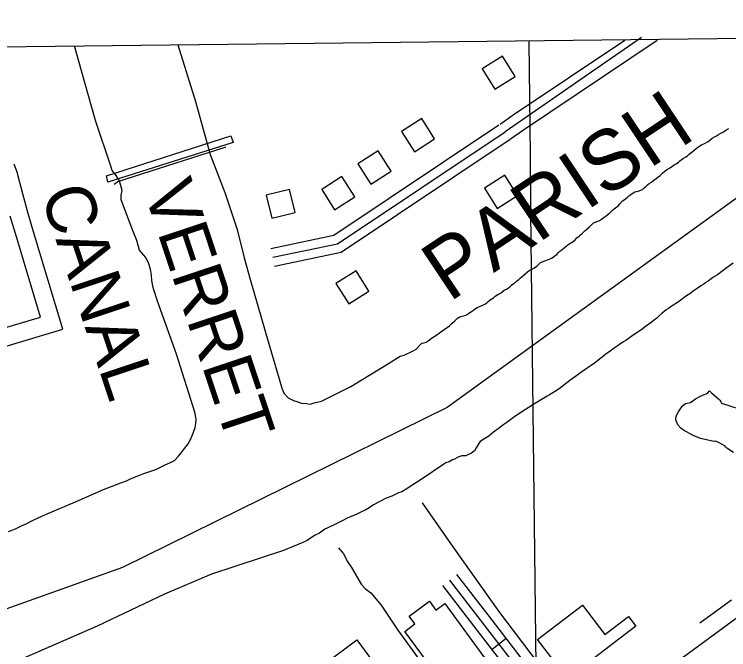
# Model space of a CAD drawing. Extents: x 3683613 to 3738215, y 469626 to 495384.
# Drawn here: x 3692076 to 3693268, y 492267 to 493327 of the extents above; entities that cross this region are included whole.
import ezdxf

# ---------------------------------------------------------------- set-up
doc = ezdxf.new("R2010")
doc.units = 0
for name, color, linetype in [('V-BLDG-OTLN', 7, 'Continuous'), ('V-BRDG-OTLN', 7, 'Continuous'), ('V-GRID-FRAM', 7, 'Continuous'), ('V-GRID-MAJR', 7, 'Continuous'), ('V-RIVR-IDEN', 7, 'Continuous'), ('V-ROAD-CNTR', 7, 'Continuous'), ('V-SITE-VEGE', 7, 'Continuous'), ('V-TOPO-BNDY', 7, 'Continuous'), ('V-TOPO-GNAM-IDEN', 7, 'Continuous'), ('V-TOPO-SHOR', 7, 'Continuous'), ('V-UTIL-LINE', 7, 'Continuous')]:
    doc.layers.add(name, color=color, linetype=linetype)

msp = doc.modelspace()

# ---------------------------------------------------------------- linework, layer by layer
at = {"layer": 'V-BLDG-OTLN'}
for points in [[(3692877.856, 493202.391), (3692911.6520000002, 493223.789), (3692890.254, 493257.58400000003), (3692856.458, 493236.186)], [(3692743.515, 493097.955), (3692777.287, 493119.389), (3692755.853, 493153.161), (3692722.08, 493131.727)], [(3692670.679, 493044.028), (3692704.451, 493065.462), (3692683.017, 493099.234), (3692649.244, 493077.8)], [(3692610.262, 493001.244), (3692644.034, 493022.678), (3692622.6, 493056.45), (3692588.827, 493035.016)], [(3692894.276, 493058.68), (3692860.438, 493037.35000000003), (3692881.767, 493003.512), (3692915.606, 493024.841)], [(3692505.5640000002, 492986.867), (3692544.426, 492996.341), (3692534.951, 493035.20300000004), (3692496.09, 493025.728)], [(3692646.339, 492899.224), (3692612.501, 492877.89400000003), (3692633.83, 492844.056), (3692667.669, 492865.385)], [(3692865.046, 492247.397), (3692799.69, 492199.335), (3692727.338, 492297.717), (3692744.161, 492310.087), (3692734.586, 492323.104), (3692768.593, 492348.114), (3692779.472, 492333.315), (3692794.003, 492343.999)], [(3693113.251, 492306.466), (3692998.881, 492218.881), (3692949.041, 492283.96), (3693023.977, 492341.349), (3693061.511, 492292.335), (3693100.9450000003, 492322.534)], [(3692735.381, 492043.693), (3692589.87, 492240.74700000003), (3692647.522, 492283.319), (3692707.71, 492201.809), (3692724.4080000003, 492214.14), (3692742.899, 492189.097), (3692727.58, 492177.784), (3692794.41, 492087.283)]]:
    msp.add_lwpolyline(points, close=True, dxfattribs=at)
at = {"layer": 'V-BRDG-OTLN'}
msp.add_lwpolyline([(3692229.611, 493057.613), (3692437.292, 493124.447), (3692440.731, 493113.66000000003), (3692231.7800000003, 493047.244)], close=True, dxfattribs=at)
at = {"layer": 'V-GRID-FRAM'}
msp.add_lwpolyline([(3687651.682, 493221.841), (3719350.328, 493590.697), (3719569.827, 475409.35000000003), (3687855.3140000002, 475040.309), (3687651.682, 493221.841)], dxfattribs=at)
at = {"layer": 'V-GRID-MAJR'}
msp.add_spline([(3693141.066, 475101.816), (3693072.329, 481160.385), (3693003.5700000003, 487220.886), (3692934.811, 493281.396), (3692934.789, 493283.31700000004)], degree=3, dxfattribs=at)
at = {"layer": 'V-ROAD-CNTR'}
msp.add_line((3692896.8781673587, 492285.79540232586), (3692873.1312148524, 492267.46243899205), dxfattribs=at)
for points in [[(3693122.6167158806, 493288.8473962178), (3692895.1381708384, 493131.217711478)], [(3693094.86177139, 493283.85040621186), (3692908.588143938, 493158.7866563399)], [(3693148.670663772, 493283.8434062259), (3692925.6741097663, 493134.1287056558)], [(3692908.589143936, 493158.7866563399), (3692886.5951879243, 493143.54668682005)], [(3692503.991953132, 492936.556100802), (3692609.240742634, 492958.5700567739), (3692884.4231922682, 493142.59668872)], [(3692925.675109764, 493134.1287056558), (3692903.6811537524, 493118.88873613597)], [(3692507.06294699, 492921.87413016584), (3692615.150730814, 492944.48208494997), (3692895.1381708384, 493131.217711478)], [(3692510.1339408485, 492907.19215952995), (3692621.060718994, 492930.3941131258), (3692903.461154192, 493118.7387364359)], [(3692062.166341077, 492773.4993945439), (3692156.7476849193, 492802.0505830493), (3692106.191259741, 492970.1267586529), (3692097.685753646, 492998.984228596), (3692089.7038363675, 493027.9019485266), (3692082.210668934, 493057.00364306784), (3692080.9012971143, 493062.3173644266), (3692080.4506362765, 493063.9245098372), (3692080.004188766, 493065.42695452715), (3692079.528816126, 493066.927312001), (3692079.0288159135, 493068.41893943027), (3692078.4990069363, 493069.91083334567), (3692077.9440018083, 493071.3888491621), (3692077.3665370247, 493072.8510425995), (3692076.7623255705, 493074.30642495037), (3692076.1300982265, 493075.7571823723), (3692075.4760194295, 493077.1873071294)], [(3693012.5609359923, 492122.6987285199), (3693890.1881807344, 492767.3854391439), (3694199.0795629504, 492985.8460022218), (3694277.94440522, 493044.8208842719)], [(3692053.6796589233, 492802.2746054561), (3692119.386315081, 492822.1094169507), (3692077.438740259, 492961.56524134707), (3692068.836246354, 492990.75177140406)], [(3692996.989967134, 492111.176751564), (3692927.9571052, 492220.99053193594), (3692802.6533558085, 492383.3022073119)], [(3692866.324228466, 492325.3723231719), (3692814.5263320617, 492392.4681889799)], [(3692842.578275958, 492307.0403598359), (3692790.780379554, 492374.13622564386)], [(3693009.6889417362, 492119.15973559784), (3692940.2720805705, 492229.58551474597), (3692866.323228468, 492325.37332316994)], [(3692984.290992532, 492103.19376752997), (3692915.6421298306, 492212.3955491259), (3692842.5772759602, 492307.04135983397)]]:
    msp.add_lwpolyline(points, dxfattribs=at)
at = {"layer": 'V-SITE-VEGE'}
msp.add_lwpolyline([(3693275.965, 492596.37), (3693264.914, 492603.12700000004), (3693262.9760000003, 492605.59500000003), (3693261.819, 492607.235), (3693249.955, 492613.612), (3693245.575, 492614.94800000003), (3693243.555, 492614.606), (3693227.98, 492617.878), (3693221.203, 492619.68700000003), (3693208.889, 492624.471), (3693192.679, 492633.38800000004), (3693188.358, 492636.728), (3693183.293, 492642.102), (3693179.9280000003, 492650.64), (3693179.6210000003, 492653.864), (3693180.944, 492657.841), (3693184.771, 492664.962), (3693191.065, 492674.018), (3693196.003, 492677.891), (3693204.088, 492679.66000000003), (3693212.698, 492685.434), (3693220.87, 492690.01300000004), (3693224.544, 492691.914), (3693227.79, 492693.02400000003), (3693231.452, 492694.523), (3693233.491, 492695.668), (3693235.9960000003, 492698.805), (3693239.906, 492695.076), (3693250.8850000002, 492685.911), (3693253.222, 492683.433), (3693255.159, 492680.963), (3693256.292, 492678.52), (3693301.2660000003, 492663.93200000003)], dxfattribs=at)
at = {"layer": 'V-TOPO-BNDY'}
msp.add_lwpolyline([(3693656.843302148, 493291.71905653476), (3692798.101177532, 492671.42973931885), (3692256.1794217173, 492404.1458018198), (3691475.0630859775, 492125.56068865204), (3691044.2578277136, 491992.0943891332), (3690569.2766779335, 491705.80691178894), (3690167.234385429, 491293.53288560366), (3689620.055476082, 490480.6831808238), (3689391.3841074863, 490221.66020227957), (3689222.686803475, 490096.86700584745), (3688304.4662702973, 489656.3013151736), (3687696.061298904, 489259.3810567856)], dxfattribs=at)
at = {"layer": 'V-TOPO-SHOR'}
msp.add_line((3693272.856, 492349.875), (3693220.097, 492311.467), dxfattribs=at)
for points in [[(3692348.5371485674, 493276.4951704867), (3692377.8510000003, 493181.783), (3692402.62, 493093.365), (3692427.272, 493029.938), (3692447.469, 492967.976), (3692459.3370000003, 492920.798), (3692469.8880000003, 492883.359), (3692499.593, 492781.407), (3692518.963, 492714.99100000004), (3692521.981, 492703.356), (3692525.41, 492694.9), (3692532.856, 492687.523), (3692541.773, 492682.902), (3692547.078, 492681.022), (3692555.1380000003, 492678.518), (3692563.1890000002, 492677.92), (3692569.548, 492676.89), (3692576.3170000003, 492679.04000000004), (3692588.588, 492681.639), (3692637.4, 492706.01), (3692700.127, 492744.637), (3692719.556, 492757.01300000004), (3692726.114, 492758.527), (3692740.485, 492765.369), (3692746.188, 492768.78500000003), (3692753.356, 492776.021), (3692755.6750000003, 492778.57300000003), (3692759.271, 492779.224), (3692762.867, 492780.088), (3692766.67, 492782.224), (3692773.42, 492787.973), (3692779.122, 492791.60000000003), (3692793.057, 492801.41000000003), (3692802.1350000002, 492807.382)], [(3692066.041, 492464.164), (3692077.6720000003, 492468.66500000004), (3692087.8140000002, 492473.585), (3692096.481, 492477.43700000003), (3692106.198, 492482.776), (3692116.7660000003, 492487.697), (3692125.644, 492491.33900000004), (3692130.504, 492493.69200000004), (3692138.536, 492497.329), (3692177.643, 492513.82), (3692224.782, 492534.16000000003), (3692253.745, 492545.732), (3692263.049, 492548.74), (3692270.8680000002, 492552.588), (3692283.551, 492557.733), (3692292.009, 492560.94800000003), (3692300.046, 492563.74), (3692308.291, 492566.531), (3692312.944, 492568.245), (3692327.313, 492575.514), (3692336.191, 492579.368), (3692343.162, 492583.001), (3692349.906, 492590.235), (3692354.539, 492596.397), (3692360.015, 492602.777), (3692366.122, 492610.43), (3692369.27, 492616.586), (3692372.83, 492625.71), (3692377.434, 492637.59500000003), (3692378.46, 492644.799), (3692379.273, 492652.004), (3692377.102, 492663.219), (3692346.365, 492760.083), (3692314.8200000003, 492848.471), (3692308.1580000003, 492868.984), (3692306.864, 492874.272), (3692305.34, 492882.949), (3692304.875, 492892.054), (3692303.134, 492901.789), (3692300.126, 492911.09500000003), (3692294.9930000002, 492921.66000000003), (3692291.159, 492926.09), (3692284.559, 492933.684), (3692280.037, 492949.974), (3692273.825, 492964.771), (3692254.306, 493017.63), (3692254.269, 493025.678), (3692255.502, 493033.52), (3692250.9820000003, 493049.173), (3692245.432, 493058.467), (3692239.251, 493066.911), (3692237.109, 493071.984), (3692211.117, 493150.229), (3692187.856, 493233.14900000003), (3692176.0302372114, 493274.487822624)], [(3692327.313, 492575.514), (3692336.191, 492579.368), (3692343.162, 492583.001), (3692349.906, 492590.235), (3692354.539, 492596.397), (3692360.015, 492602.777), (3692366.122, 492610.43), (3692369.27, 492616.586), (3692372.83, 492625.71), (3692377.434, 492637.59500000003), (3692378.46, 492644.799), (3692379.273, 492652.004), (3692377.102, 492663.219), (3692346.365, 492760.083), (3692314.8200000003, 492848.471), (3692308.1580000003, 492868.984), (3692306.864, 492874.272), (3692305.34, 492882.949), (3692304.875, 492892.054), (3692303.134, 492901.789), (3692300.126, 492911.09500000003), (3692294.9930000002, 492921.66000000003), (3692291.159, 492926.09), (3692284.559, 492933.684), (3692280.037, 492949.974), (3692273.825, 492964.771), (3692254.306, 493017.63), (3692254.269, 493025.678), (3692255.502, 493033.52), (3692250.9820000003, 493049.173), (3692245.432, 493058.467), (3692239.251, 493066.911), (3692237.109, 493071.984), (3692211.117, 493150.229), (3692187.856, 493233.14900000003), (3692176.0302372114, 493274.487822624)], [(3693153.642, 493058.444), (3693157.703, 493062.071), (3693161.557, 493065.704), (3693164.75, 493068.109), (3693168.342, 493069.874), (3693171.535, 493072.278), (3693174.0870000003, 493074.077), (3693177.0670000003, 493076.278), (3693180.241, 493078.058), (3693184.065, 493080.651), (3693186.414, 493082.664), (3693192.5810000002, 493087.061), (3693196.599, 493089.232), (3693199.157, 493091.239), (3693201.94, 493093.862), (3693206.841, 493097.672), (3693209.6180000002, 493100.088), (3693214.31, 493103.90400000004), (3693217.49, 493105.892), (3693220.048, 493107.897), (3693222.598, 493109.695), (3693227.653, 493111.629), (3693234.001, 493115.188), (3693240.614, 493120.613), (3693244.225, 493123.003), (3693247.608, 493124.777), (3693250.992, 493126.55), (3693254.8030000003, 493128.727), (3693259.452, 493131.08900000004), (3693263.488, 493133.882), (3693268.365, 493136.862)], [(3692802.1350000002, 492807.382), (3692806.43, 492811.83400000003), (3692810.7120000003, 492815.871), (3692813.0700000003, 492818.091), (3692815.626, 492820.098), (3692818.177, 492821.896), (3692823.4390000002, 492823.821), (3692827.42, 492824.745), (3692830.361, 492825.699), (3692833.5500000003, 492827.895), (3692836.095, 492829.484), (3692838.651, 492831.49100000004), (3692842.262, 492833.881), (3692845.248, 492836.292), (3692848.414, 492837.862), (3692853.903, 492840.408), (3692857.487, 492841.967), (3692860.87, 492843.74), (3692864.272, 492846.136), (3692866.83, 492848.143), (3692869.822, 492850.761), (3692872.5810000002, 492852.553), (3692875.339, 492854.34500000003), (3692878.323, 492856.753), (3692882.784, 492859.745), (3692887.433, 492862.107), (3692889.997, 492864.32), (3692893.4050000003, 492866.92600000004), (3692896.995, 492868.693), (3692902.0840000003, 492871.873), (3692905.725, 492875.304), (3692908.93, 492878.124), (3692912.123, 492880.526), (3692914.6750000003, 492882.324), (3692917.659, 492884.735), (3692920.651, 492887.352), (3692924.077, 492890.582), (3692928.3540000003, 492894.41000000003), (3692932.4050000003, 492897.621), (3692934.754, 492899.632), (3692938.7660000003, 492901.596), (3692943.8370000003, 492904.152), (3692948.316, 492907.767), (3692951.105, 492910.599), (3692954.091, 492913.01), (3692961.261, 492916.12700000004), (3692967.157, 492918.451), (3692970.1, 492919.406), (3692973.483, 492921.177), (3692978.1750000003, 492924.995), (3692981.143, 492926.78), (3692983.9450000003, 492930.028), (3692986.3000000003, 492932.249), (3692989.274, 492934.24100000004), (3692993.537, 492937.655), (3692996.949, 492940.467), (3692999.714, 492942.468), (3693002.7, 492944.879), (3693005.461, 492946.67100000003), (3693008.213, 492948.254), (3693011.8340000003, 492951.061), (3693014.839, 492954.09500000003), (3693018.253, 492956.908), (3693020.821, 492959.329), (3693024.032, 492962.358), (3693028.738, 492966.58900000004), (3693031.509, 492968.797), (3693035.986, 492972.412), (3693038.575, 492975.457), (3693042.651, 492979.50200000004), (3693049.384, 492982.009), (3693052.333, 492983.17), (3693055.7290000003, 492985.359), (3693059.987, 492988.564), (3693063.395, 492991.169), (3693066.794, 492993.568), (3693069.5670000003, 492995.775), (3693071.714, 492998.00200000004), (3693074.29, 493000.631), (3693079.185, 493004.234), (3693081.534, 493006.24700000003), (3693083.887, 493008.467), (3693086.2630000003, 493011.31), (3693090.563, 493015.971), (3693093.744, 493017.957), (3693098.436, 493021.775), (3693101.213, 493024.189), (3693104.6210000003, 493026.79600000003), (3693108.451, 493029.596), (3693111.406, 493030.966), (3693117.065, 493032.256), (3693124.22, 493034.96), (3693127.225, 493037.993), (3693129.576, 493040.004), (3693132.566, 493042.623), (3693135.558, 493045.24100000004), (3693139.16, 493047.424), (3693143.639, 493051.039), (3693146.1890000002, 493052.837), (3693150.019, 493055.636), (3693153.642, 493058.444)], [(3693275.6580000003, 492912.25200000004), (3693265.446, 492904.852), (3693258.846, 492899.843), (3693249.271, 492892.841), (3693244.389, 492889.65400000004), (3693241.202, 492887.45900000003), (3693236.742, 492884.469), (3693233.549, 492882.064), (3693230.147, 492879.666), (3693226.538, 492877.276), (3693222.721, 492874.89), (3693213.5870000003, 492868.707), (3693210.185, 492866.309), (3693206.5700000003, 492863.71), (3693203.156, 492860.896), (3693197.848, 492857.306), (3693193.809, 492854.51300000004), (3693188.065, 492850.31), (3693184.032, 492847.723), (3693173.626, 492840.746), (3693167.6750000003, 492836.55), (3693163.8570000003, 492834.166), (3693157.238, 492828.532), (3693152.112, 492824.104), (3693147.842, 492820.483), (3693141.87, 492815.664), (3693137.3910000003, 492812.049), (3693129.953, 492806.858), (3693125.267, 492803.249), (3693119.944, 492799.243), (3693116.336, 492796.851), (3693110.181, 492792.87), (3693102.522, 492787.26900000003), (3693096.148, 492782.878), (3693092.544, 492780.694), (3693088.298, 492777.905), (3693082.132, 492773.50800000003), (3693077.036, 492770.119), (3693072.5700000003, 492766.922), (3693069.805, 492764.92100000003), (3693063.6380000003, 492760.52400000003), (3693059.59, 492757.31200000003), (3693054.683, 492753.294), (3693043.83, 492745.289), (3693038.507, 492741.283), (3693030.2290000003, 492735.907), (3693023, 492730.70900000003), (3693019.176, 492728.114), (3693012.3540000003, 492722.697), (3693007.038, 492718.898), (3693003.001, 492716.105), (3692984.899, 492702.277), (3692977.467, 492697.292), (3692968.779, 492692.137), (3692965.177, 492689.952)], [(3693275.6580000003, 492912.25200000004), (3693265.446, 492904.852), (3693258.846, 492899.843), (3693249.271, 492892.841), (3693244.389, 492889.65400000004), (3693241.202, 492887.45900000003), (3693236.742, 492884.469), (3693233.549, 492882.064), (3693230.147, 492879.666), (3693226.538, 492877.276), (3693222.721, 492874.89), (3693213.5870000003, 492868.707), (3693210.185, 492866.309), (3693206.5700000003, 492863.71), (3693203.156, 492860.896)], [(3693203.156, 492860.896), (3693197.848, 492857.306), (3693193.809, 492854.51300000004), (3693188.065, 492850.31), (3693184.032, 492847.723), (3693173.626, 492840.746), (3693167.6750000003, 492836.55), (3693163.8570000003, 492834.166), (3693157.238, 492828.532), (3693152.112, 492824.104), (3693147.842, 492820.483), (3693141.87, 492815.664), (3693137.3910000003, 492812.049), (3693129.953, 492806.858), (3693125.267, 492803.249), (3693119.944, 492799.243), (3693116.336, 492796.851), (3693110.181, 492792.87), (3693102.522, 492787.26900000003), (3693096.148, 492782.878), (3693092.544, 492780.694), (3693088.298, 492777.905), (3693082.132, 492773.50800000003), (3693077.036, 492770.119), (3693072.5700000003, 492766.922), (3693069.805, 492764.92100000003), (3693063.6380000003, 492760.52400000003), (3693059.59, 492757.31200000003), (3693054.683, 492753.294), (3693043.83, 492745.289), (3693038.507, 492741.283), (3693030.2290000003, 492735.907), (3693023, 492730.70900000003), (3693019.176, 492728.114), (3693012.3540000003, 492722.697), (3693007.038, 492718.898), (3693003.001, 492716.105), (3692984.899, 492702.277), (3692977.467, 492697.292), (3692968.779, 492692.137), (3692965.177, 492689.952), (3692959.457, 492686.583), (3692953.737, 492683.21400000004), (3692949.71, 492680.83400000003), (3692942.725, 492676.87700000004), (3692933.597, 492670.901), (3692928.935, 492668.126), (3692922.781, 492664.145), (3692919.16, 492661.337), (3692910.882, 492655.961), (3692897.484, 492646.36600000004), (3692893.0130000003, 492642.958), (3692883.2260000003, 492635.753), (3692880.031, 492633.351), (3692875.767, 492629.93700000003), (3692871.503, 492626.525), (3692867.667, 492623.517), (3692865.1240000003, 492621.925), (3692859.611, 492618.55), (3692853.4560000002, 492614.569), (3692850.855, 492611.108), (3692849.119, 492608.66000000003), (3692846.684, 492603.737), (3692843.839, 492599.033), (3692838.522, 492595.23600000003), (3692832.808, 492592.074), (3692829.23, 492590.722), (3692826.103, 492590.605), (3692822.7770000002, 492590.706), (3692817.731, 492588.979), (3692814.342, 492586.999), (3692810.5300000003, 492584.822), (3692807.165, 492583.673), (3692804.204, 492582.094), (3692801.2430000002, 492580.517), (3692795.9960000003, 492579.005), (3692792.616, 492576.898)], [(3692965.177, 492689.952), (3692959.457, 492686.583), (3692953.737, 492683.21400000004), (3692949.71, 492680.83400000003), (3692942.725, 492676.87700000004), (3692933.597, 492670.901), (3692928.935, 492668.126), (3692922.781, 492664.145), (3692919.16, 492661.337), (3692910.882, 492655.961), (3692897.484, 492646.36600000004), (3692893.0130000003, 492642.958), (3692883.2260000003, 492635.753), (3692880.031, 492633.351), (3692875.767, 492629.93700000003), (3692871.503, 492626.525), (3692867.667, 492623.517), (3692865.1240000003, 492621.925), (3692859.611, 492618.55), (3692853.4560000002, 492614.569), (3692850.855, 492611.108), (3692849.119, 492608.66000000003), (3692846.684, 492603.737), (3692843.839, 492599.033), (3692838.522, 492595.23600000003), (3692832.808, 492592.074), (3692829.23, 492590.722), (3692826.103, 492590.605), (3692822.7770000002, 492590.706), (3692817.731, 492588.979), (3692814.342, 492586.999), (3692810.5300000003, 492584.822), (3692807.165, 492583.673), (3692804.204, 492582.094), (3692801.2430000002, 492580.517), (3692795.9960000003, 492579.005), (3692792.616, 492576.898), (3692756.514, 492552.16000000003), (3692729.696, 492534.879), (3692722.302, 492530.609), (3692716.8030000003, 492528.678), (3692705.603, 492523.541), (3692696.088, 492519.896), (3692684.89, 492513.916), (3692675.3850000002, 492508.575), (3692667.994, 492503.67), (3692661.233, 492500.037), (3692655.103, 492497.255), (3692647.497, 492493.196), (3692637.9820000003, 492489.55100000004), (3692631.009, 492486.342), (3692624.035, 492482.708), (3692618.332, 492479.716), (3692610.5100000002, 492476.292), (3692600.1580000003, 492470.949), (3692594.028, 492468.168), (3692585.162, 492461.772), (3692577.978, 492458.137), (3692573.3310000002, 492455.574), (3692564.25, 492449.603), (3692557.066, 492446.178), (3692524.933, 492432.89900000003), (3692404.813, 492393.158), (3692326.389, 492359.751), (3692213.958, 492306.49), (3692092.63, 492253.613)], [(3692066.041, 492464.164), (3692077.6720000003, 492468.66500000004), (3692087.8140000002, 492473.585), (3692096.481, 492477.43700000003), (3692106.198, 492482.776), (3692116.7660000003, 492487.697), (3692125.644, 492491.33900000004), (3692130.504, 492493.69200000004), (3692138.536, 492497.329), (3692177.643, 492513.82), (3692224.782, 492534.16000000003), (3692253.745, 492545.732), (3692263.049, 492548.74), (3692270.8680000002, 492552.588), (3692283.551, 492557.733), (3692292.009, 492560.94800000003), (3692300.046, 492563.74), (3692308.291, 492566.531), (3692312.944, 492568.245), (3692327.313, 492575.514)], [(3692792.616, 492576.898), (3692756.514, 492552.16000000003), (3692729.696, 492534.879), (3692722.302, 492530.609), (3692716.8030000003, 492528.678), (3692705.603, 492523.541), (3692696.088, 492519.896), (3692684.89, 492513.916), (3692675.3850000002, 492508.575), (3692667.994, 492503.67), (3692661.233, 492500.037), (3692655.103, 492497.255), (3692647.497, 492493.196), (3692637.9820000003, 492489.55100000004), (3692631.009, 492486.342), (3692624.035, 492482.708), (3692618.332, 492479.716), (3692610.5100000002, 492476.292), (3692600.1580000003, 492470.949), (3692594.028, 492468.168), (3692585.162, 492461.772), (3692577.978, 492458.137), (3692573.3310000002, 492455.574), (3692564.25, 492449.603), (3692557.066, 492446.178), (3692524.933, 492432.89900000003), (3692404.813, 492393.158), (3692326.389, 492359.751), (3692213.958, 492306.49), (3692092.63, 492253.613)], [(3693014.923, 492158.743), (3692886.316, 492329.072), (3692808.161, 492438.582), (3692757.045, 492512.11600000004)], [(3692616.619, 492437.37200000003), (3692625.2660000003, 492427.126), (3692628.625, 492420.99), (3692631.363, 492415.079), (3692638.33, 492404.25800000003), (3692654.37, 492376.516), (3692661.446, 492369.438), (3692671.02, 492362.286), (3692688.095, 492341.38), (3692716.009, 492299.756), (3692833.609, 492137.457), (3692849.616, 492115.543)]]:
    msp.add_lwpolyline(points, dxfattribs=at)
at = {"layer": 'V-UTIL-LINE'}
msp.add_lwpolyline([(3692242.597, 493043.69200000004), (3692248.508, 493048.167), (3692427.4250000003, 493105.55), (3692428.9080000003, 493105.76900000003)], dxfattribs=at)

# ---------------------------------------------------------------- texts
at = {"layer": 'V-RIVR-IDEN'}
for s, p in [('VERRET', (3692290.7892332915, 493034.04850115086)), ('CANAL', (3692118.8434082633, 493028.20891251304))]:
    msp.add_text(s, height=82.99983200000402, rotation=288.43490625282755, dxfattribs=at).set_placement(p)
at = {"layer": 'V-TOPO-GNAM-IDEN'}
msp.add_text('PARISH', height=99.99980199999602, rotation=33.689987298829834, dxfattribs=at).set_placement((3692801.366358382, 492845.941282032))

doc.saveas('drawing.dxf')
